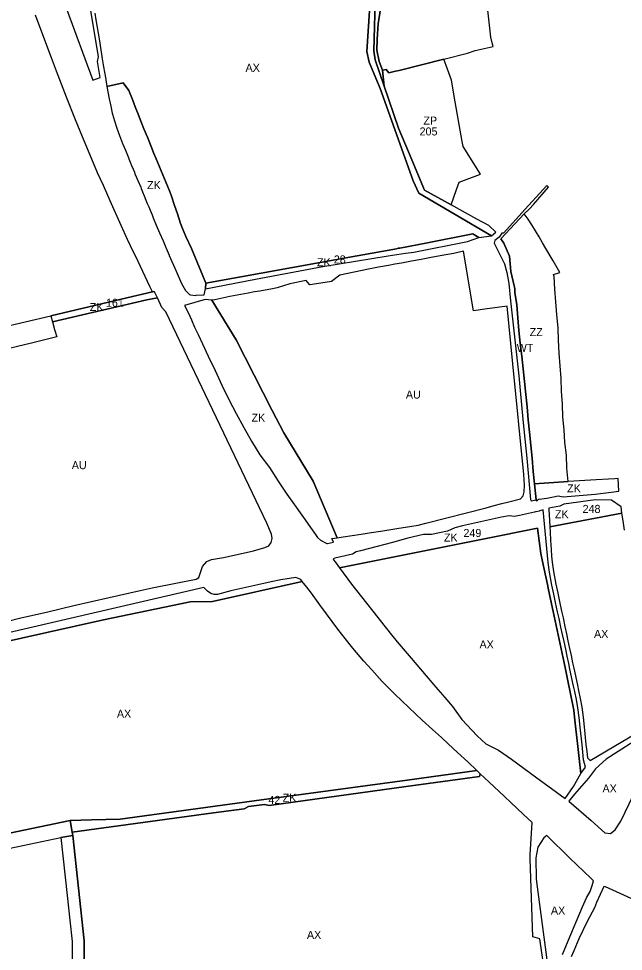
# Model space of a CAD drawing. Extents: x -521939 to -516426, y -1197857 to -1189551.
# Drawn here: x -520661 to -519905, y -1192859 to -1191694 of the extents above; entities that cross this region are included whole.
import ezdxf

# ---------------------------------------------------------------- set-up
doc = ezdxf.new("R2010")
doc.units = 0
for name, color, linetype in [('90640013', 7, 'Continuous'), ('90670013', 7, 'Continuous'), ('90680023', 7, 'Continuous'), ('90710013', 7, 'Continuous'), ('90710023', 7, 'Continuous'), ('90750013', 7, 'Continuous'), ('90760013', 7, 'Continuous'), ('ID_navrh', 7, 'Continuous')]:
    doc.layers.add(name, color=color, linetype=linetype)

msp = doc.modelspace()

# ---------------------------------------------------------------- linework, layer by layer
at = {"layer": '90640013'}
for points in [[(-520220.67, -1191658.04), (-520225.31, -1191734.79), (-520222.47, -1191747.94), (-520208.83, -1191780.88), (-520167.61, -1191896.22), (-520160.5, -1191911.69), (-520069.51, -1191964.99), (-520064.17, -1191960.26), (-520073.07, -1191952.16), (-520087.95, -1191943.96), (-520120.2, -1191926.19), (-520153.55, -1191907.81), (-520173.54, -1191860.15), (-520185.99, -1191830.46), (-520203.95, -1191777.85), (-520215.12, -1191745.09), (-520216.83, -1191733.94), (-520214.6, -1191657.89)], [(-520028.75, -1191937.49), (-520022.26, -1191931.12), (-520017.32, -1191925.76), (-519998.7, -1191904.19), (-520000.5, -1191901.98), (-520027.63, -1191931.83), (-520054.76, -1191961.68), (-520056.79, -1191961.78), (-520060.15, -1191966.67), (-520065.72, -1191970.89), (-520066.59, -1191973.96), (-520053.59, -1192000.14), (-520050.49, -1192010.79), (-520048.04, -1192024.54), (-520045.89, -1192046.26), (-520035.65, -1192139.81), (-520030.62, -1192194.2), (-520025.53, -1192242.79), (-520021.14, -1192294.19), (-520019.95, -1192296.1), (-520014.1, -1192294.81), (-520016.13, -1192274.92), (-520017.47, -1192259.12), (-520019.03, -1192242.52), (-520020.5, -1192226.62), (-520022.26, -1192210.24), (-520023.77, -1192194.61), (-520025.23, -1192178.53), (-520026.86, -1192163.12), (-520028.3, -1192146.99), (-520030.09, -1192131.09), (-520031.88, -1192115.25), (-520033.73, -1192099.21), (-520035.38, -1192083.39), (-520036.61, -1192067.31), (-520038.17, -1192051.31), (-520040.45, -1192035.64), (-520040.74, -1192030.74), (-520041.45, -1192027.63), (-520045.7, -1192009.5), (-520047.42, -1191990.31), (-520054.46, -1191974.14), (-520057.98, -1191968.6), (-520028.75, -1191937.49)]]:
    msp.add_lwpolyline(points, dxfattribs=at)
at = {"layer": '90670013'}
for points in [[(-520208.37, -1191681.55), (-520211.37, -1191700.36), (-520212.41, -1191719.43), (-520212.79, -1191733.19), (-520210.26, -1191747.11), (-520205.83, -1191758.24), (-520201.52, -1191757.27), (-520197.9, -1191761.48), (-520189.75, -1191759.39), (-520185.24, -1191758.27), (-520129.36, -1191744.38), (-520099.5, -1191736.96), (-520090.26, -1191733.61), (-520067.79, -1191728.38), (-520068.89, -1191723.89), (-520070.57, -1191717.02), (-520080.29, -1191629.67)], [(-519974.08, -1192271.75), (-519975.65, -1192255.26), (-519975.91, -1192238.9), (-519977.93, -1192223.26), (-519978.93, -1192207.14), (-519980.71, -1192191.27), (-519981.11, -1192175.33), (-519982.11, -1192158.98), (-519982.81, -1192143.22), (-519983.95, -1192127.23), (-519985.01, -1192111.53), (-519985.9, -1192095.45), (-519986.54, -1192079.78), (-519988.1, -1192063.56), (-519989.4, -1192047.4), (-519990.77, -1192031.55), (-519991.22, -1192015.6), (-519992.06, -1192013.41), (-519984.18, -1192010.67), (-519992.78, -1191996.05), (-520001.71, -1191980.85), (-520005.98, -1191973.6), (-520010.35, -1191966.15), (-520019.18, -1191951.14), (-520023.97, -1191944.31), (-520028.75, -1191937.49), (-520057.98, -1191968.6), (-520054.46, -1191974.14), (-520047.42, -1191990.31), (-520045.7, -1192009.5), (-520041.45, -1192027.63), (-520040.74, -1192030.74), (-520040.45, -1192035.64), (-520038.17, -1192051.31), (-520036.61, -1192067.31), (-520035.38, -1192083.39), (-520033.73, -1192099.21), (-520031.88, -1192115.25), (-520030.09, -1192131.09), (-520028.3, -1192146.99), (-520026.86, -1192163.12), (-520025.23, -1192178.53), (-520023.77, -1192194.61), (-520022.26, -1192210.24), (-520020.5, -1192226.62), (-520019.03, -1192242.52), (-520017.47, -1192259.12), (-520016.13, -1192274.92), (-519974.08, -1192271.75)]]:
    msp.add_lwpolyline(points, dxfattribs=at)
at = {"layer": '90680023'}
msp.add_lwpolyline([(-520120.2, -1191926.19), (-520113.38, -1191906.91), (-520110.14, -1191897.75), (-520096.72, -1191892.86), (-520083.3, -1191887.96), (-520105.09, -1191853.21), (-520106.18, -1191847.24), (-520114.94, -1191797.7), (-520119.69, -1191770.62), (-520124.76, -1191756.84), (-520129.36, -1191744.38), (-520185.24, -1191758.27), (-520189.75, -1191759.39), (-520197.9, -1191761.48), (-520201.52, -1191757.27), (-520205.83, -1191758.24), (-520203.95, -1191777.85), (-520185.99, -1191830.46), (-520173.54, -1191860.15), (-520153.55, -1191907.81), (-520120.2, -1191926.19)], dxfattribs=at)
at = {"layer": '90710013'}
for points in [[(-520214.6, -1191657.89), (-520216.83, -1191733.94), (-520215.12, -1191745.09), (-520203.95, -1191777.85), (-520205.83, -1191758.24), (-520210.26, -1191747.11), (-520212.79, -1191733.19), (-520212.41, -1191719.43), (-520211.37, -1191700.36), (-520208.37, -1191681.55)], [(-520426.95, -1192031.34), (-520426.72, -1192023.92), (-520430.29, -1192014.85), (-520444.65, -1191980.87), (-520451.54, -1191965.8), (-520455.86, -1191955.88), (-520458.36, -1191949.37), (-520462.16, -1191937.49), (-520465.65, -1191927.09), (-520469.56, -1191915.55), (-520471.91, -1191908.58), (-520480.17, -1191888.95), (-520488.64, -1191868.83), (-520491.4, -1191862.29), (-520494.97, -1191853.41), (-520499.69, -1191841.81), (-520503.92, -1191831.34), (-520506.95, -1191823.72), (-520511.23, -1191813.07), (-520514.9, -1191803.65), (-520518.39, -1191794.8), (-520522.87, -1191783.33), (-520529.84, -1191774.04), (-520550.3, -1191778.29), (-520547.27, -1191793.71), (-520545.36, -1191803.05), (-520543.6, -1191811.69), (-520543.32, -1191813.06), (-520540.91, -1191821.42), (-520537.93, -1191830.32), (-520534.33, -1191839.76), (-520530.55, -1191849.48), (-520530.18, -1191850.44), (-520527.05, -1191858.16), (-520522.92, -1191868.36), (-520522.68, -1191868.97), (-520519.36, -1191877.12), (-520517.43, -1191881.88), (-520515.96, -1191885.49), (-520515.15, -1191887.48), (-520508.05, -1191904.38), (-520507.4, -1191905.91), (-520505.77, -1191909.89), (-520503.68, -1191914.99), (-520501.41, -1191920.55), (-520499.82, -1191924.41), (-520498, -1191928.82), (-520496.32, -1191932.89), (-520493.89, -1191938.79), (-520492.35, -1191942.53), (-520492.29, -1191942.67), (-520488.52, -1191951.69), (-520484.6, -1191961.08), (-520480.14, -1191971.36), (-520476.54, -1191979.67), (-520476.27, -1191980.29), (-520472.43, -1191989.16), (-520472.36, -1191989.33), (-520463.71, -1192009.09), (-520456.96, -1192024.37), (-520451.84, -1192033.1), (-520446.9, -1192038.37), (-520445.83, -1192038.53), (-520439.75, -1192039.45), (-520438.66, -1192038.99), (-520428.58, -1192038.61), (-520426.95, -1192031.34)], [(-520274.54, -1192349.23), (-520267.02, -1192347.71), (-520269.2, -1192343.04), (-520262.42, -1192342.12), (-520292.51, -1192271.49), (-520329.07, -1192211.04), (-520343.59, -1192182.98), (-520354.91, -1192161.12), (-520388.91, -1192094.81), (-520419.12, -1192045.34), (-520427.58, -1192044.36), (-520453.11, -1192052.05), (-520452.5, -1192053.26), (-520451.85, -1192054.55), (-520448.65, -1192060.89), (-520444.67, -1192070.07), (-520440.7, -1192079.25), (-520436.41, -1192088.25), (-520430.99, -1192099.66), (-520423.57, -1192115.27), (-520415.17, -1192133.35), (-520406.75, -1192151.4), (-520397.97, -1192169.26), (-520388.67, -1192186.84), (-520379.14, -1192204.29), (-520369.38, -1192221.59), (-520359.31, -1192238.71), (-520347.07, -1192254.47), (-520336.34, -1192271.22), (-520325.37, -1192287.72), (-520313.94, -1192303.92), (-520308.83, -1192311.12), (-520302.69, -1192319.77), (-520295.99, -1192329.24), (-520289.68, -1192338.14), (-520287.05, -1192341.84), (-520283.19, -1192345.02), (-520275.44, -1192349.46), (-520274.54, -1192349.23)], [(-519974.08, -1192271.75), (-520016.13, -1192274.92), (-520014.1, -1192294.81), (-520013.84, -1192295.89), (-520012.06, -1192295.49), (-520011.84, -1192294.83), (-520011.44, -1192294.25), (-520010.62, -1192293.75), (-520010.19, -1192293.71), (-520000.5, -1192292.44), (-519992.31, -1192290.88), (-519986.42, -1192289.86), (-519980.27, -1192290.99), (-519960.37, -1192289.48), (-519940.37, -1192287.51), (-519920.13, -1192284.98), (-519910.66, -1192283.8), (-519911.44, -1192268.22), (-519915.44, -1192268.38), (-519923.64, -1192268.7), (-519938.81, -1192269.62), (-519974.08, -1192271.75)], [(-520728.34, -1192483.53), (-520554.6, -1192444.53), (-520446.27, -1192421.97), (-520418.25, -1192421.67), (-520306.33, -1192396.84), (-520307.78, -1192394.28), (-520314.08, -1192391.89), (-520332.75, -1192394.51), (-520345.17, -1192397.26), (-520361.57, -1192400.9), (-520395.48, -1192408.42), (-520412.04, -1192413.12), (-520416.34, -1192412.93), (-520420.44, -1192411.62), (-520424.5, -1192408.81), (-520429.27, -1192404.08), (-520729.45, -1192473.76)], [(-520592.85, -1192713.96), (-520607.67, -1192716.44), (-520599.87, -1192788.81), (-520596.56, -1192819.53), (-520593.65, -1192846.53), (-520593.65, -1192886.47)], [(-520578.65, -1193022.99), (-520578.65, -1192845.72), (-520592.85, -1192713.96)]]:
    msp.add_lwpolyline(points, dxfattribs=at)
at = {"layer": '90710023'}
for points in [[(-520085.46, -1191967.04), (-520093.1, -1191962.36), (-520149.53, -1191973.51), (-520184.43, -1191980.26), (-520186.17, -1191980.57), (-520188.39, -1191981.03), (-520249.07, -1191991.95), (-520426.72, -1192023.92), (-520426.95, -1192031.34), (-520364.5, -1192019.1), (-520280.31, -1192003.2), (-520198.94, -1191990.1), (-520177.25, -1191986.81), (-520166.67, -1191985.2), (-520099.84, -1191971.93), (-520085.46, -1191967.04)], [(-520618.37, -1192072.35), (-520500.53, -1192045.04), (-520487.08, -1192042.46), (-520490.69, -1192035.01), (-520493.41, -1192035.03), (-520525.18, -1192042.5), (-520620.5, -1192064.91), (-520618.37, -1192072.35)], [(-519906.74, -1192311.24), (-519907.89, -1192303.65), (-519919.82, -1192295.13), (-519939.67, -1192294.88), (-519979.44, -1192300.11), (-519984.39, -1192302.69), (-519998.15, -1192305.25), (-519998.28, -1192306.62), (-519997.42, -1192320.41), (-519996.92, -1192328.48), (-519906.74, -1192311.24)], [(-519952.4, -1192628.52), (-519954.63, -1192619.45), (-519955.64, -1192609.73), (-519956.62, -1192600.81), (-519958.97, -1192578.79), (-519960.25, -1192566.55), (-519961.77, -1192554.51), (-519963.65, -1192543.99), (-519965.8, -1192533.95), (-519967.19, -1192527.44), (-519971.66, -1192506.17), (-519973.23, -1192499.19), (-519975.18, -1192490), (-519977.05, -1192481.41), (-519979.09, -1192471.82), (-519981, -1192462.94), (-519982.92, -1192453.96), (-519985.25, -1192443.1), (-519987.07, -1192434.66), (-519989.57, -1192422.89), (-519991.79, -1192412.45), (-519994.19, -1192401.25), (-519997.31, -1192384.9), (-519998.98, -1192372.94), (-520005.28, -1192307.33), (-520009.17, -1192308.52), (-520010.2, -1192308.83), (-520013.73, -1192309.6), (-520014.95, -1192309.86), (-520015.86, -1192310.06), (-520034.73, -1192314.14), (-520041.17, -1192315.39), (-520047.46, -1192314.76), (-520057.05, -1192316.46), (-520105.95, -1192327.26), (-520115.51, -1192329.52), (-520124.86, -1192333.87), (-520144.55, -1192338.08), (-520154.82, -1192337.98), (-520174.07, -1192342.77), (-520193.4, -1192348.01), (-520212.74, -1192353.2), (-520233.56, -1192358.34), (-520238.84, -1192359.64), (-520243.36, -1192362.72), (-520265.64, -1192367.66), (-520267.65, -1192368.23), (-520267.03, -1192369.46), (-520264.96, -1192372.31), (-520259.75, -1192379.49), (-520080.47, -1192343.75), (-520012.45, -1192330.19), (-520008.24, -1192361.89), (-520006.07, -1192371.92), (-519999.94, -1192400.62), (-519999.03, -1192404.87), (-519994.83, -1192424.53), (-519992.75, -1192434.33), (-519979.09, -1192498.16), (-519977.31, -1192506.28), (-519975.1, -1192516.62), (-519966.68, -1192557.39), (-519965.84, -1192566), (-519964.65, -1192577.41), (-519961.87, -1192602.8), (-519958.27, -1192636.72), (-519952.4, -1192628.52)], [(-520593.8, -1192709.96), (-520416.9, -1192685.81), (-520378.59, -1192680.58), (-520373.25, -1192677.83), (-520353.27, -1192675.1), (-520347.39, -1192676.32), (-520176.35, -1192652.97), (-520084.86, -1192640.48), (-520083.77, -1192636.81), (-520088.02, -1192632.83), (-520175.03, -1192644.71), (-520356.96, -1192669.55), (-520533.69, -1192693.68), (-520569.38, -1192694.51), (-520596.04, -1192695.13), (-520593.8, -1192709.96)], [(-520592.85, -1192713.96), (-520593.8, -1192709.96), (-520596.04, -1192695.13), (-520758.3, -1192728.9), (-520815.45, -1192740.8), (-520834.88, -1192746.05), (-520874.84, -1192756.86), (-520946.38, -1192779.22), (-520947.19, -1192790.27), (-520944.08, -1192798.91), (-520934.56, -1192796.95), (-520930.47, -1192795.56), (-520873.66, -1192776.25), (-520770.76, -1192750.7), (-520767.25, -1192749.83), (-520766.41, -1192749.65), (-520607.67, -1192716.44), (-520592.85, -1192713.96)]]:
    msp.add_lwpolyline(points, dxfattribs=at)
at = {"layer": '90750013'}
for points in [[(-520493.41, -1192035.03), (-520496.63, -1192028.24), (-520511.32, -1191997.09), (-520520.62, -1191977.39), (-520524.4, -1191969.39), (-520532.26, -1191951.92), (-520545.99, -1191921.37), (-520554.58, -1191902.23), (-520561.8, -1191886.19), (-520568.92, -1191869.32), (-520580.78, -1191841.33), (-520589.45, -1191820.06), (-520600.61, -1191791.87), (-520613.34, -1191759.5), (-520619.58, -1191742.71), (-520632.82, -1191707.09), (-520639.25, -1191689.54)], [(-520104.53, -1191984.27), (-520116.89, -1191987.05), (-520129.2, -1191989.31), (-520144.97, -1191992.17), (-520157.4, -1191994.44), (-520169.8, -1191996.69), (-520182.23, -1191998.96), (-520190.36, -1192000.43), (-520198.5, -1192001.91), (-520211.03, -1192004.19), (-520223.56, -1192006.45), (-520259.31, -1192014.22), (-520269.44, -1192022.05), (-520282.86, -1192024.02), (-520296.64, -1192026.13), (-520301.24, -1192020.66), (-520321.68, -1192025.09), (-520337.55, -1192029.72), (-520343.38, -1192031.33), (-520359.07, -1192034), (-520365.78, -1192035.12), (-520373.61, -1192036.43), (-520396.61, -1192040.92), (-520415.23, -1192044.95), (-520419.12, -1192045.34), (-520388.91, -1192094.81), (-520354.91, -1192161.12), (-520343.59, -1192182.98), (-520329.07, -1192211.04), (-520292.51, -1192271.49), (-520262.42, -1192342.12), (-520254.9, -1192340.88), (-520232.72, -1192337.5), (-520222.7, -1192335.85), (-520205.45, -1192333.29), (-520195.42, -1192331.76), (-520185.37, -1192330.24), (-520171.64, -1192328.13), (-520161.54, -1192326.38), (-520151.67, -1192323.97), (-520076.52, -1192304.58), (-520066.54, -1192302), (-520056.72, -1192299.47), (-520048.15, -1192297.25), (-520033.35, -1192293.31), (-520030.2, -1192289.65), (-520028.85, -1192284.58), (-520028.62, -1192276.52), (-520029.31, -1192262.91), (-520042.86, -1192124.96), (-520050, -1192052.77), (-520078.17, -1192056.59), (-520092.32, -1192058.51), (-520104.53, -1191984.27)], [(-520684.93, -1192080.06), (-520620.5, -1192064.91), (-520525.18, -1192042.5), (-520493.41, -1192035.03)], [(-520674.16, -1192446.1), (-520659.49, -1192442.68), (-520624.25, -1192434.52), (-520591.42, -1192426.87), (-520547.23, -1192416.63), (-520521.69, -1192410.69), (-520508.74, -1192407.91), (-520493.5, -1192404.76), (-520464.05, -1192398.85), (-520438.72, -1192393.79), (-520435.18, -1192391.83), (-520430.97, -1192378.16), (-520425.51, -1192371.59), (-520419.59, -1192369.13), (-520404.73, -1192366.86), (-520379.97, -1192361.36), (-520367.27, -1192358.55), (-520352.85, -1192354.32), (-520348.08, -1192352.07), (-520344.8, -1192347.99), (-520343.61, -1192342.88), (-520344.77, -1192337.74), (-520350.34, -1192323.78), (-520413.24, -1192192.22), (-520476.52, -1192059.92), (-520481.41, -1192054.32), (-520487.08, -1192042.46), (-520500.53, -1192045.04), (-520618.37, -1192072.35)], [(-520618.37, -1192072.35), (-520615.67, -1192081.81), (-520612.97, -1192091.26), (-520644.57, -1192098.88), (-520690.33, -1192109.89)]]:
    msp.add_lwpolyline(points, dxfattribs=at)
at = {"layer": '90760013'}
for points in [[(-520655.62, -1191516.43), (-520647.74, -1191541.74), (-520645.29, -1191547.71), (-520634.42, -1191576.76), (-520624.44, -1191610.86), (-520620.11, -1191625.25), (-520604.04, -1191671.07), (-520600.77, -1191681.45), (-520567.63, -1191770.59), (-520558.71, -1191767.21), (-520562, -1191747.31), (-520560.94, -1191741.4), (-520571.31, -1191678.64), (-520572.92, -1191668.76), (-520583.24, -1191606.18), (-520593.47, -1191543.67), (-520594.55, -1191539), (-520597.37, -1191520.53), (-520655.62, -1191516.43)], [(-520085.46, -1191967.04), (-520069.51, -1191964.99), (-520160.5, -1191911.69), (-520167.61, -1191896.22), (-520208.83, -1191780.88), (-520222.47, -1191747.94), (-520225.31, -1191734.79), (-520220.67, -1191658.04)], [(-520565.37, -1191686.86), (-520564, -1191695.24), (-520560.08, -1191719.1), (-520557.81, -1191732.77), (-520555.95, -1191744), (-520554.32, -1191753.79), (-520552.16, -1191767), (-520550.3, -1191778.29), (-520529.84, -1191774.04), (-520522.87, -1191783.33), (-520518.39, -1191794.8), (-520514.9, -1191803.65), (-520511.23, -1191813.07), (-520506.95, -1191823.72), (-520503.92, -1191831.34), (-520499.69, -1191841.81), (-520494.97, -1191853.41), (-520491.4, -1191862.29), (-520488.64, -1191868.83), (-520480.17, -1191888.95), (-520471.91, -1191908.58), (-520469.56, -1191915.55), (-520465.65, -1191927.09), (-520462.16, -1191937.49), (-520458.36, -1191949.37), (-520455.86, -1191955.88), (-520451.54, -1191965.8), (-520444.65, -1191980.87), (-520430.29, -1192014.85), (-520426.72, -1192023.92), (-520249.07, -1191991.95), (-520188.39, -1191981.03), (-520186.17, -1191980.57), (-520184.43, -1191980.26), (-520149.53, -1191973.51), (-520093.1, -1191962.36), (-520085.46, -1191967.04)], [(-519903.52, -1192332.49), (-519905.16, -1192320.75), (-519906.74, -1192311.24), (-519996.92, -1192328.48), (-519996.45, -1192335.23), (-519995.98, -1192345.16), (-519995.09, -1192356.86), (-519994.62, -1192364.98), (-519994.01, -1192372.39), (-519992.38, -1192384.09), (-519989.29, -1192400.26), (-519986.9, -1192411.41), (-519984.68, -1192421.85), (-519982.18, -1192433.61), (-519980.36, -1192442.05), (-519978.03, -1192452.91), (-519976.11, -1192461.89), (-519974.2, -1192470.77), (-519972.16, -1192480.36), (-519970.29, -1192488.95), (-519968.35, -1192498.12), (-519966.77, -1192505.11), (-519962.3, -1192526.4), (-519960.91, -1192532.9), (-519958.74, -1192543.03), (-519956.83, -1192553.76), (-519955.28, -1192565.98), (-519954, -1192578.27), (-519951.65, -1192600.27), (-519950.67, -1192609.2), (-519949.86, -1192616.95), (-519946.53, -1192620.31), (-519878.04, -1192579.76)], [(-519977.84, -1192667.57), (-519967.07, -1192652.71), (-519958.27, -1192636.72), (-519961.87, -1192602.8), (-519964.65, -1192577.41), (-519965.84, -1192566), (-519966.68, -1192557.39), (-519975.1, -1192516.62), (-519977.31, -1192506.28), (-519979.09, -1192498.16), (-519992.75, -1192434.33), (-519994.83, -1192424.53), (-519999.03, -1192404.87), (-519999.94, -1192400.62), (-520006.07, -1192371.92), (-520008.24, -1192361.89), (-520012.45, -1192330.19), (-520080.47, -1192343.75), (-520259.75, -1192379.49), (-520244.47, -1192400.09), (-520232.33, -1192415.78), (-520211.73, -1192441.71), (-520208.64, -1192445.57), (-520194.58, -1192463.28), (-520187.51, -1192472.01), (-520170.22, -1192492.58), (-520144.14, -1192523.08), (-520136.69, -1192531.64), (-520128.18, -1192541.53), (-520118.39, -1192552.66), (-520106.61, -1192568.96), (-520087.56, -1192589.6), (-520076.96, -1192599.48), (-520061.16, -1192607.27), (-520044.56, -1192618.55), (-520014.61, -1192640.84), (-519977.84, -1192667.57)], [(-520758.3, -1192728.9), (-520596.04, -1192695.13), (-520569.38, -1192694.51), (-520533.69, -1192693.68), (-520356.96, -1192669.55), (-520175.03, -1192644.71), (-520088.02, -1192632.83), (-520099.47, -1192621.84), (-520112.32, -1192610.16), (-520123.66, -1192599.39), (-520132.06, -1192591.63), (-520143.43, -1192581.71), (-520156.21, -1192570), (-520164.14, -1192562.58), (-520190.54, -1192537.37), (-520206.14, -1192521.43), (-520219.35, -1192507.19), (-520229.16, -1192496.14), (-520242.91, -1192479.92), (-520252.63, -1192468), (-520261.71, -1192456.26), (-520275.92, -1192437.11), (-520284.01, -1192425.9), (-520294.74, -1192411.1), (-520300.6, -1192403.76), (-520306.33, -1192396.84), (-520418.25, -1192421.67), (-520446.27, -1192421.97), (-520554.6, -1192444.53), (-520728.34, -1192483.53)], [(-519973.13, -1192671.04), (-519945.35, -1192695.43), (-519928.14, -1192710.54), (-519920.96, -1192711.64), (-519915.4, -1192706.96), (-519907.96, -1192696.03), (-519907.66, -1192695.43), (-519897.61, -1192674.42), (-519889.55, -1192656.44), (-519887.28, -1192650.8), (-519877.84, -1192627.03), (-519873.78, -1192613.72), (-519872.16, -1192604.77), (-519871.43, -1192589.64), (-519876.72, -1192586.93), (-519926.45, -1192618.64), (-519939.66, -1192630.65), (-519948.49, -1192642.24), (-519965.83, -1192662.43), (-519973.13, -1192671.04)], [(-520004.11, -1192880.48), (-520009.13, -1192843.07), (-520017.97, -1192840.72), (-520021.35, -1192743.3), (-520021.45, -1192737.96), (-520018.8, -1192697.81), (-520030.09, -1192687.16), (-520045.5, -1192672.63), (-520053.58, -1192665.11), (-520073.19, -1192646.74), (-520083.77, -1192636.81), (-520084.86, -1192640.48), (-520176.35, -1192652.97), (-520347.39, -1192676.32), (-520353.27, -1192675.1), (-520373.25, -1192677.83), (-520378.59, -1192680.58), (-520416.9, -1192685.81), (-520593.8, -1192709.96)], [(-520593.8, -1192709.96), (-520592.85, -1192713.96), (-520578.65, -1192845.72), (-520578.65, -1193022.99)], [(-519981.06, -1192862.78), (-519973.79, -1192845.48), (-519956.08, -1192803.22), (-519950.92, -1192792.01), (-519946.43, -1192783.81), (-519944.02, -1192776.33), (-519942.19, -1192770.64), (-519945.61, -1192767.46), (-519971.98, -1192742.48), (-520000.53, -1192714.15), (-520004.15, -1192716.76), (-520011.85, -1192728.35), (-520014.48, -1192741.68), (-520013.94, -1192768.6), (-520012.68, -1192778.14), (-520003.51, -1192847.12), (-519985.11, -1192985.35)], [(-519717.76, -1192873.41), (-519752.94, -1192857.37), (-519788.21, -1192841.3), (-519805.68, -1192833.36), (-519819.07, -1192827.26), (-519848.77, -1192813.79), (-519927.45, -1192777.89), (-519929.51, -1192777.57), (-519938.48, -1192797.62), (-519941.05, -1192804.31), (-519950.26, -1192821.29), (-519960.56, -1192843.19), (-519966.94, -1192857.93), (-519970.35, -1192865.66)]]:
    msp.add_lwpolyline(points, dxfattribs=at)

# ---------------------------------------------------------------- texts
at = {"layer": '90640013'}
msp.add_text('WT', height=10, rotation=360, dxfattribs=at).set_placement((-520038.19, -1192109.88))
at = {"layer": '90670013'}
msp.add_text('ZZ', height=10, rotation=0, dxfattribs=at).set_placement((-520022.04, -1192090.28))
at = {"layer": '90680023'}
msp.add_text('ZP', height=10, rotation=0, dxfattribs=at).set_placement((-520154.76, -1191825.98))
at = {"layer": '90710013'}
for rotation, p in [(360, (-520500.03, -1191906.64)), (0, (-520369.54, -1192197.11)), (360, (-519975.21, -1192285.3))]:
    msp.add_text('ZK', height=10, rotation=rotation, dxfattribs=at).set_placement(p)
at = {"layer": '90710023'}
for rotation, p in [(360, (-520287.73, -1192002.91)), (0, (-520571.64, -1192058.85)), (360, (-519990.51, -1192317.65)), (360, (-520129.17, -1192346.86)), (360, (-520330.54, -1192671.83))]:
    msp.add_text('ZK', height=10, rotation=rotation, dxfattribs=at).set_placement(p)
at = {"layer": '90750013'}
msp.add_text('AU', height=10, dxfattribs=at).set_placement((-520176.67, -1192168.24))
msp.add_text('AU', height=10, rotation=0, dxfattribs=at).set_placement((-520594.1, -1192256.41))
at = {"layer": '90760013'}
for rotation, p in [(0, (-520377.01, -1191760.13)), (360, (-519941.63, -1192467.13)), (0, (-520084.69, -1192480.37)), (360, (-520537.73, -1192566.84)), (360, (-519931.04, -1192660.22)), (0, (-519995.48, -1192812.67)), (0, (-520300.29, -1192843.11))]:
    msp.add_text('AX', height=10, rotation=rotation, dxfattribs=at).set_placement(p)
at = {"layer": 'ID_navrh'}
for s, rotation, p in [('205', 360, (-520159.56, -1191839.58)), ('28', 360, (-520266.74, -1191999.46)), ('161', 0, (-520551.43, -1192053.52)), ('248', 0, (-519955.88, -1192311.04)), ('249', 0, (-520104.73, -1192341.12)), ('42', 360, (-520348.51, -1192674.5))]:
    msp.add_text(s, height=10, rotation=rotation, dxfattribs=at).set_placement(p)

doc.saveas('drawing.dxf')
